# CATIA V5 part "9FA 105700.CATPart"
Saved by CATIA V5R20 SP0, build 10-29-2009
Part number: 9FA 105700
Revision: ANY
Definition: UNKNOWN
Nomenclature: 9FA 105700
Source: Unknown
Bounding box of the stored display mesh (mm): x -5 to 5, y -10 to 10, z -5 to 5
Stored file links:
  C:\Users\Utente\Desktop\IO LAVORO\3D X SITO CF\CUMSA\3D files FA\FA 105700\9FA 105700.CATPart

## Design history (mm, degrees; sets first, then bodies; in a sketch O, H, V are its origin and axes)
Body1 "Redondeo2" (main body)
  Solid1: solid without history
